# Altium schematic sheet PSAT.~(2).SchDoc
size 381 x 241 mm; SheetNumber: 1; SheetTotal: 2
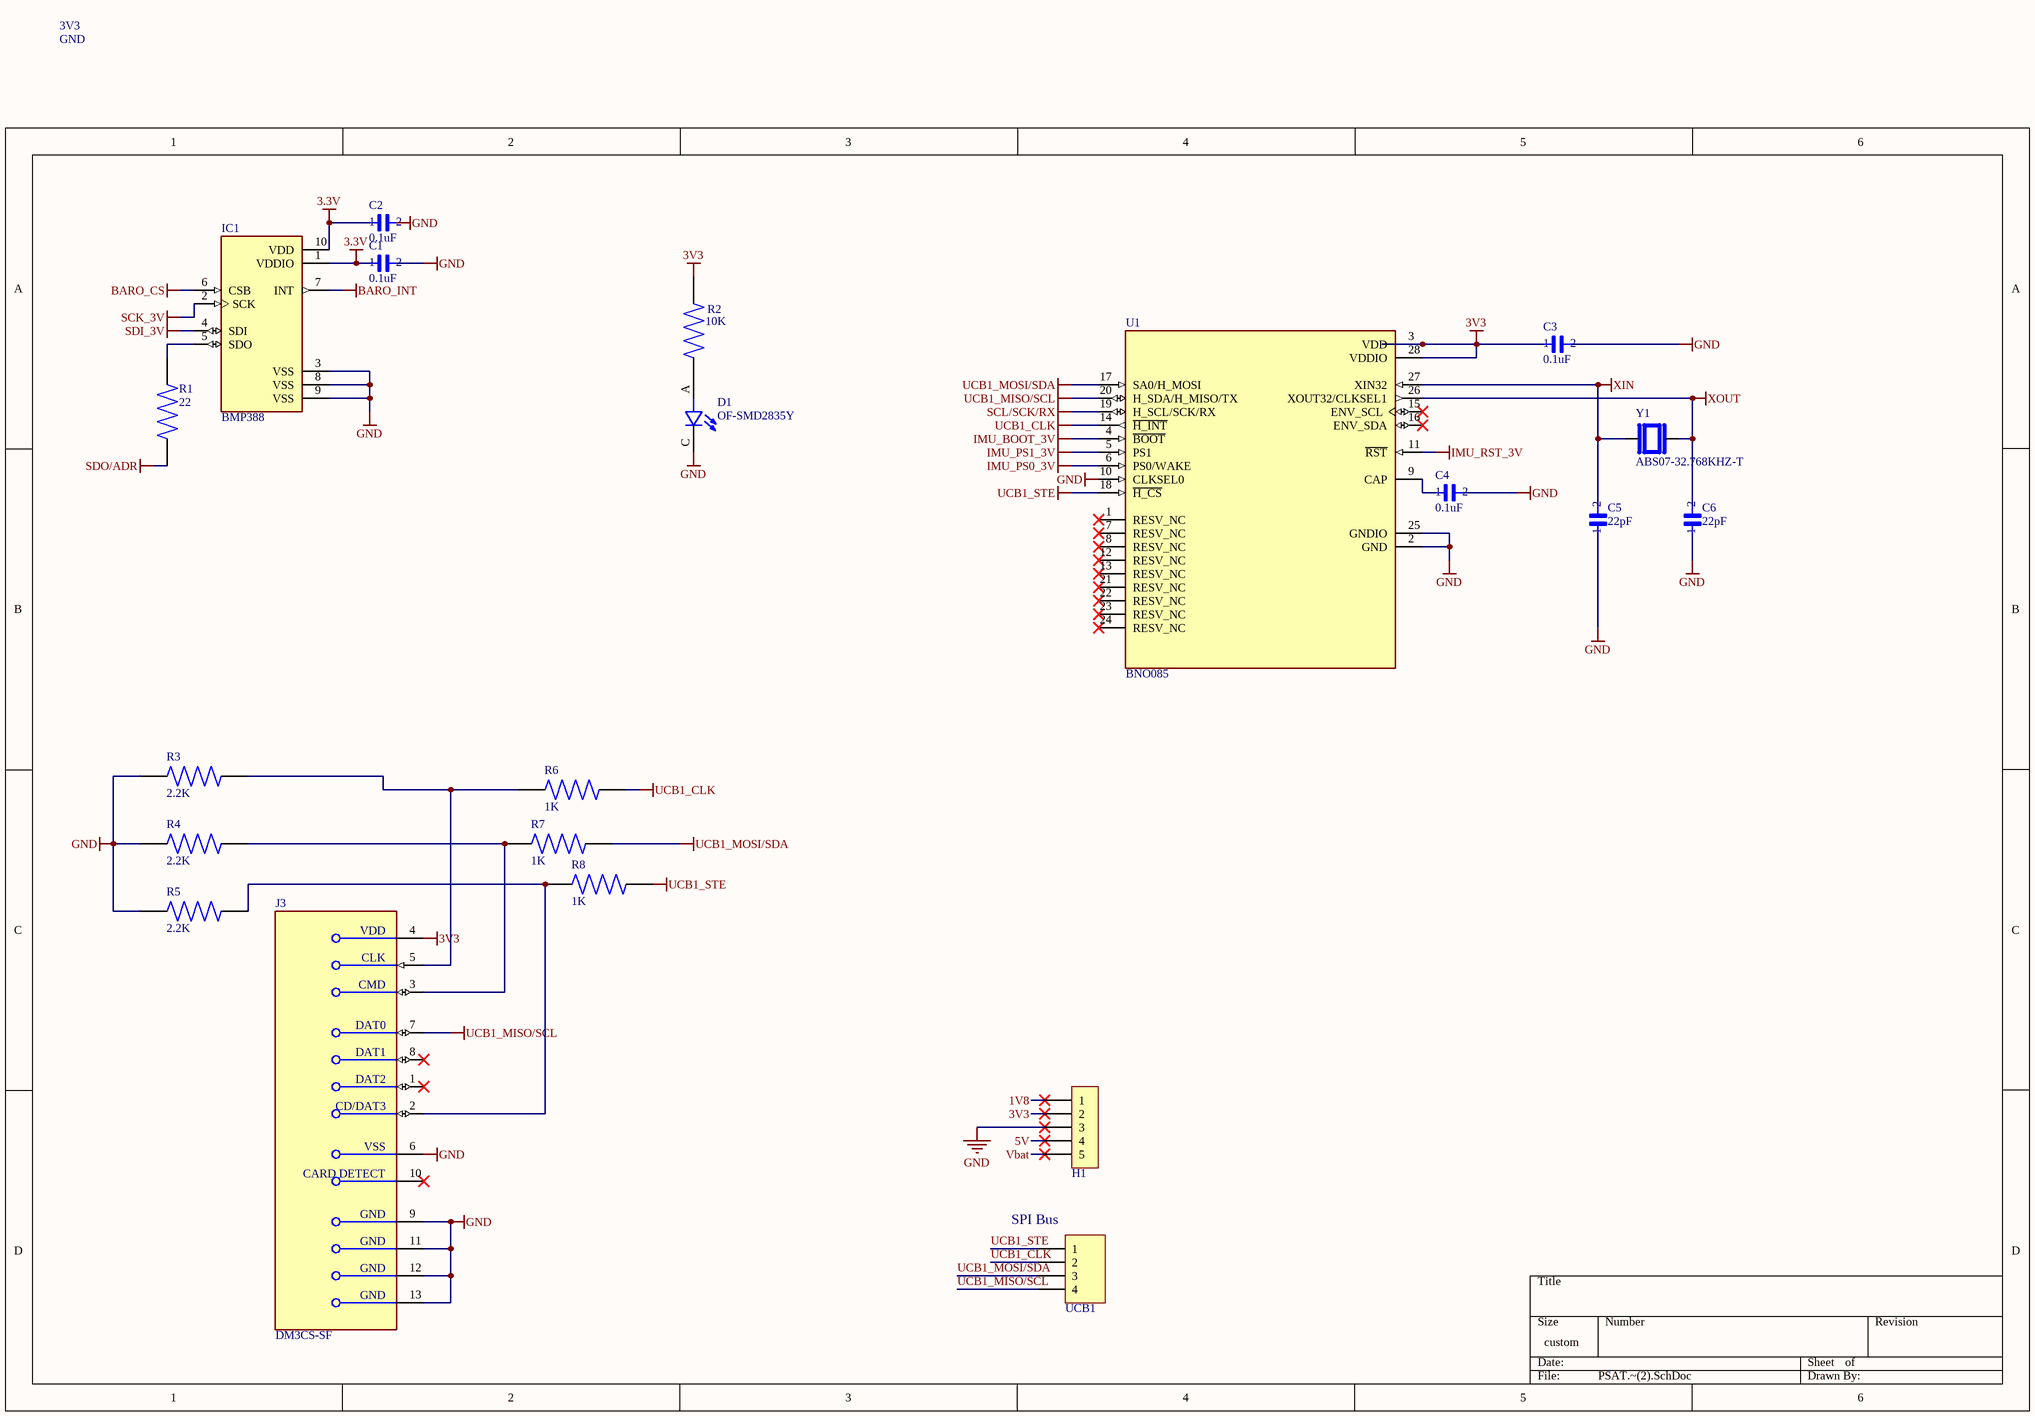
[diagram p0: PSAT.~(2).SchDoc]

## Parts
C1  0.1uF  [0603]
C2  0.1uF  [0603]
C3  0.1uF  [0603]
C4  0.1uF  [0603]
C5  22pF  [0603]
C6  22pF  [0603]
D1  OF-SMD2835Y  [LED_OF-SMD2835Y]
H1  Header - 2.54mm,1x5-pin  [HEADER_2.54MM_1x5PIN]  (value not drawn)  (no BOM)
IC1  BMP388  [PQFN50P200X200X80-10N]
J3  DM3CS-SF  [FP-DM3CS-SF-MFG]
R1  22  [RESC1607X60N]
R2  10K  [RESC1607X60N]
R3  2.2K  [RESC1607X60N]
R4  2.2K  [RESC1607X60N]
R5  2.2K  [RESC1607X60N]
R6  1K  [RESC1607X60N]
R7  1K  [RESC1607X60N]
R8  1K  [RESC1607X60N]
U1  BNO085  [IC_BNO085]
UCB1  Header 4  [HDR1X4]  (value not drawn)  (no BOM)
Y1  ABS07-32.768KHZ-T  [XTAL_ABS07-32.768KHZ-T]

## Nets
3.3V: C1.1 C2.1 IC1.1(VDDIO) IC1.10(VDD)
3V3: C3.1 H1.2 J3.4(VDD) R2.2 U1.3(VDD) U1.28(VDDIO)
BARO_CS: IC1.6(CSB)
BARO_INT: IC1.7(INT)
GND: C1.2 C2.2 C3.2 C4.2 C5.1 C6.1 D1.C H1.3 IC1.3(VSS) IC1.8(VSS) IC1.9(VSS) J3.6(VSS) J3.9(GND) J3.11(GND) J3.12(GND) J3.13(GND) R3.2 R4.2 R5.2 U1.2(GND) U1.10(CLKSEL0) U1.25(GNDIO)
IMU_BOOT_3V: U1.4(~{BOOT})
IMU_PS0_3V: U1.6(PS0/WAKE)
IMU_PS1_3V: U1.5(PS1)
IMU_RST_3V: U1.11(~{RST})
SCK_3V: IC1.2(SCK)
SCL/SCK/RX: U1.19(H_SCL/SCK/RX)
SDI_3V: IC1.4(SDI)
SDO/ADR: R1.1
UCB1_CLK: R6.1 U1.14(~{H_INT}) UCB1.2
UCB1_MISO/SCL: J3.7(DAT0) U1.20(H_SDA/H_MISO/TX) UCB1.4
UCB1_MOSI/SDA: R7.1 U1.17(SA0/H_MOSI) UCB1.3
UCB1_STE: R8.1 U1.18(~{H_CS}) UCB1.1
XIN: C5.2 U1.27(XIN32) Y1.1
XOUT: C6.2 U1.26(XOUT32/CLKSEL1) Y1.2
1V8: H1.1
5V: H1.4
Vbat: H1.5
NetC4_1: C4.1 U1.9(CAP)
NetD1_A: D1.A R2.1
NetIC1_5: IC1.5(SDO) R1.2
NetJ3_2: J3.2(CD/DAT3) R5.1 R8.2
NetJ3_3: J3.3(CMD) R4.1 R7.2
NetJ3_5: J3.5(CLK) R3.1 R6.2

Not connected (* = marked no-connect by the designer): J3 1(DAT2)* 8(DAT1)* 10(CARD_DETECT)*; U1 1(RESV_NC)* 7(RESV_NC)* 8(RESV_NC)* 12(RESV_NC)* 13(RESV_NC)* 15(ENV_SCL)* 16(ENV_SDA)* 21(RESV_NC)* 22(RESV_NC)* 23(RESV_NC)* 24(RESV_NC)*

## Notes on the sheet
- 3V3
- GND
- (near UCB1) SPI Bus

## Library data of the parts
C1-C6 = C0603: 0 Ohms Jumper 0.1W, 1/10W Chip Resistor 0603 (1608 Metric) Moisture Resistant Thick Film; MF: Yageo
D1 = OF-SMD2835Y: LED; SMD; 2835, PLCC2; yellow; 2200-2800mcd; 2.8x3.5x0.75mm; 120Â°
IC1 = BMP388: P-Sensor SPI I2C 1, 25 Bar SMD
J3 = CMP-11597-000003-1: CONN MICRO SD CARD HINGED TYPE; Pitch: 1.1mm; Connector Type: Connector; Current Rating: 500mA; Voltage Rating (AC): 125V; Gender: Female; Insulation Resistance: 1GR; Number of Positions: 8; Contact Resistance: 100mR
R1-R8 = RC0603JR-070RL: 0 Ohms Jumper 0.1W, 1/10W Chip Resistor 0603 (1608 Metric) Moisture Resistant Thick Film; MF: Yageo
U1 = BNO085: Accelerometer, Gyroscope, Magnetometer, 9 Axis Sensor IÂ²C, SPI, UART Output; MF: Hillcrest Laboratories,
UCB1 = Header 4: Header, 4-Pin
Y1 = ABS07-32.768KHZ-T: 32.768 kHz Â±20ppm Crystal 12.5pF 70 kOhms 2-SMD, No Lead; MF: Abracon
